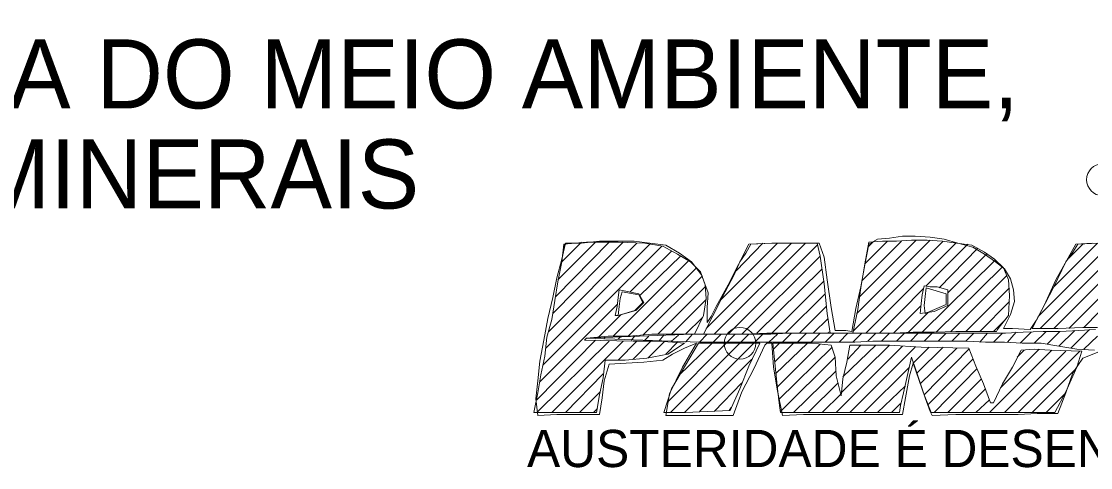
# Model space of a CAD drawing. Extents: x -4 to 42046, y -3 to 29697.
# Drawn here: x 33632 to 34171, y 1139 to 1364 of the extents above; entities that cross this region are included whole.
import ezdxf

# ---------------------------------------------------------------- set-up
doc = ezdxf.new("R2010")
doc.units = 0
doc.header["$LTSCALE"] = 32
doc.header["$PDMODE"] = 32
doc.header["$PDSIZE"] = 16
for name, color, linetype, lineweight in [('12', 7, 'Continuous', 13), ('50', 7, 'Continuous', 13), ('51', 7, 'Continuous', 13)]:
    doc.layers.add(name, color=color, linetype=linetype, lineweight=lineweight)
doc.layers.add('53', color=7, linetype='Continuous')

msp = doc.modelspace()

# ---------------------------------------------------------------- linework, layer by layer
at = {"layer": '12'}
for points in [[(34091.29, 1165.53), (34090.29, 1167.53), (34087.79, 1174.53), (34081.79, 1192.03), (34079.79, 1185.53), (34077.79, 1174.53), (34076.29, 1166.03), (34066.29, 1166.03), (34055.79, 1166.03), (34045.29, 1166.03), (34035.79, 1166.03), (34026.29, 1166.03), (34015.79, 1165.53), (34013.29, 1178.03), (34011.29, 1190.03), (34010.29, 1202.03), (34009.29, 1202.03), (34007.79, 1202.03), (34006.79, 1201.03), (34001.29, 1189.03), (33995.29, 1177.53), (33990.79, 1165.53), (33979.29, 1165.53), (33968.29, 1165.53), (33956.79, 1165.53), (33958.79, 1176.53), (33965.29, 1190.03), (33972.29, 1202.03), (33966.29, 1199.53), (33960.29, 1196.53), (33955.29, 1193.53), (33945.79, 1192.53), (33936.79, 1192.03), (33928.29, 1191.53), (33925.79, 1183.03), (33924.79, 1174.53), (33923.29, 1166.03), (33912.29, 1166.03), (33901.79, 1166.03), (33892.29, 1165.53), (33891.29, 1174.03), (33892.29, 1183.03), (33893.29, 1193.03), (33895.29, 1203.53), (33897.29, 1214.53), (33899.79, 1225.03), (33901.79, 1235.03), (33904.29, 1244.53), (33906.29, 1252.53), (33914.29, 1252.53), (33923.29, 1253.53), (33932.29, 1253.53), (33940.79, 1253.53), (33948.79, 1252.53), (33956.79, 1251.53), (33963.79, 1247.53), (33969.79, 1243.03), (33974.79, 1236.53), (33978.29, 1227.53), (33977.79, 1220.03), (33977.79, 1215.53), (33977.79, 1212.53), (33979.79, 1215.53), (33982.29, 1220.53), (33988.29, 1231.53), (33998.79, 1252.03), (34010.29, 1252.53), (34022.29, 1252.53), (34034.29, 1252.53), (34036.79, 1245.53), (34038.29, 1234.03), (34040.29, 1220.03), (34042.29, 1208.53), (34045.29, 1208.53), (34047.79, 1208.53), (34050.79, 1208.03), (34052.79, 1219.53), (34055.29, 1230.53), (34057.29, 1241.53), (34059.29, 1252.03), (34063.79, 1254.53), (34069.79, 1255.03), (34076.29, 1256.03), (34082.79, 1256.03), (34090.29, 1255.53), (34097.29, 1254.53), (34104.29, 1252.53), (34111.79, 1250.53), (34117.79, 1247.03), (34123.29, 1243.03), (34127.79, 1239.53), (34130.79, 1234.53), (34132.29, 1229.03), (34132.79, 1223.03), (34130.79, 1216.53), (34127.29, 1209.53), (34131.79, 1209.53)], [(34131.79, 1209.53), (34140.79, 1209.03), (34143.79, 1213.53), (34147.79, 1221.03), (34153.79, 1234.03), (34163.79, 1252.03), (34172.29, 1252.53)], [(34176.29, 1198.03), (34167.29, 1194.53), (34162.29, 1187.03), (34158.79, 1177.03), (34154.79, 1166.53), (34144.29, 1166.53), (34134.79, 1166.03), (34123.79, 1166.03), (34113.29, 1166.03), (34103.29, 1166.03), (34091.29, 1165.53)]]:
    msp.add_lwpolyline(points, dxfattribs=at)
for points in [[(33932.79, 1216.03), (33933.29, 1220.53), (33933.79, 1224.53), (33934.79, 1228.03), (33943.29, 1226.53), (33945.29, 1222.53), (33941.29, 1218.53)], [(34087.79, 1217.03), (34087.29, 1221.03), (34087.79, 1225.53), (34088.29, 1230.03), (34098.29, 1227.03), (34098.29, 1221.53)]]:
    msp.add_lwpolyline(points, close=True, dxfattribs=at)
at = {"layer": '50'}
for p, q in [((33897.79, 1208.03), (33942.29, 1252.53)), ((33899.79, 1217.03), (33935.29, 1253.03)), ((33901.29, 1225.53), (33928.29, 1253.03)), ((33902.29, 1234.03), (33921.29, 1253.03)), ((33904.29, 1243.03), (33914.29, 1253.03)), ((33977.29, 1209.53), (34020.29, 1252.53)), ((33981.29, 1206.53), (34027.29, 1252.53)), ((33984.79, 1224.03), (34013.29, 1252.53)), ((33992.29, 1238.53), (34005.79, 1252.53)), ((34051.29, 1208.03), (34096.79, 1253.53)), ((34053.29, 1217.03), (34090.29, 1254.03)), ((34054.79, 1225.53), (34083.29, 1254.03)), ((34055.79, 1233.53), (34075.79, 1253.53)), ((34057.29, 1242.03), (34068.79, 1253.53)), ((34057.79, 1207.03), (34103.29, 1252.53)), ((34058.79, 1250.53), (34061.29, 1253.03)), ((34144.79, 1215.53), (34181.79, 1252.53)), ((34145.79, 1209.53), (34188.79, 1252.53)), ((34152.79, 1230.53), (34174.79, 1252.53)), ((34152.79, 1209.53), (34195.79, 1252.53)), ((33894.79, 1191.03), (33954.79, 1251.03)), ((33896.29, 1199.53), (33948.79, 1252.03)), ((33905.29, 1251.03), (33906.29, 1252.03)), ((33938.79, 1228.03), (33959.79, 1248.53)), ((33988.29, 1206.53), (34033.29, 1251.53)), ((34088.29, 1231.03), (34109.29, 1252.03)), ((34094.79, 1230.03), (34114.29, 1250.03)), ((34099.29, 1227.53), (34118.79, 1247.03)), ((34160.29, 1245.03), (34167.29, 1252.03)), ((34160.29, 1209.53), (34198.79, 1248.03)), ((33930.29, 1205.53), (33968.29, 1243.53)), ((33943.79, 1226.03), (33964.29, 1246.03)), ((33995.29, 1206.53), (34034.79, 1246.03)), ((34086.29, 1207.53), (34123.29, 1244.03)), ((34167.79, 1210.03), (34200.29, 1243.03)), ((33937.79, 1205.53), (33972.29, 1240.03)), ((33945.29, 1206.03), (33975.29, 1236.03)), ((34002.79, 1207.03), (34035.79, 1239.53)), ((34093.29, 1207.53), (34126.79, 1240.53)), ((34100.79, 1208.03), (34128.79, 1236.03)), ((34010.29, 1207.03), (34036.79, 1233.53)), ((33952.79, 1206.53), (33976.79, 1230.53)), ((34017.29, 1207.03), (34037.29, 1227.03)), ((34064.79, 1207.03), (34086.79, 1229.53)), ((34108.29, 1208.03), (34130.29, 1230.03)), ((33893.29, 1182.53), (33932.29, 1221.53)), ((33959.79, 1206.53), (33977.29, 1224.03)), ((34024.29, 1207.03), (34037.79, 1220.53)), ((34071.79, 1207.03), (34085.79, 1221.03)), ((34115.29, 1208.03), (34130.29, 1223.03)), ((33922.79, 1205.03), (33934.29, 1216.53)), ((33966.79, 1206.53), (33975.29, 1215.03)), ((34031.29, 1207.03), (34038.79, 1214.53)), ((34079.29, 1207.53), (34089.29, 1217.53)), ((34122.29, 1208.03), (34128.29, 1214.03)), ((34038.29, 1207.03), (34039.79, 1208.03)), ((33891.79, 1173.53), (33921.29, 1203.53)), ((33891.79, 1167.03), (33928.29, 1203.03)), ((33899.29, 1167.03), (33935.29, 1203.03)), ((33932.79, 1193.53), (33942.29, 1203.03)), ((33940.29, 1194.03), (33949.29, 1203.03)), ((33947.79, 1194.53), (33956.29, 1203.03)), ((33956.79, 1196.53), (33962.79, 1202.53)), ((33957.79, 1172.53), (33987.29, 1202.03)), ((33959.29, 1167.03), (33994.29, 1202.03)), ((33963.29, 1185.53), (33980.29, 1202.03)), ((33966.29, 1167.03), (34001.29, 1202.03)), ((34011.29, 1199.03), (34014.29, 1202.03)), ((34011.79, 1192.53), (34021.29, 1202.03)), ((34012.29, 1186.53), (34028.29, 1202.03)), ((34013.29, 1180.03), (34034.79, 1201.53)), ((34013.79, 1173.53), (34040.79, 1200.03)), ((34042.79, 1167.03), (34076.29, 1200.53)), ((34045.29, 1177.03), (34069.79, 1201.03)), ((34046.29, 1185.03), (34062.79, 1201.03)), ((34048.79, 1194.03), (34055.29, 1201.03)), ((34049.79, 1167.03), (34082.79, 1200.03)), ((34081.79, 1192.03), (34089.79, 1200.03)), ((34083.79, 1187.03), (34096.79, 1200.03)), ((34085.29, 1181.53), (34103.79, 1199.53)), ((34087.29, 1176.03), (34109.79, 1199.03)), ((34120.29, 1167.03), (34151.79, 1198.53)), ((34125.79, 1179.53), (34145.29, 1199.03)), ((34134.29, 1195.03), (34137.79, 1198.53)), ((33973.79, 1167.53), (34000.29, 1194.03)), ((34014.79, 1167.53), (34042.29, 1195.03)), ((34089.29, 1171.03), (34111.79, 1194.03)), ((34127.79, 1167.03), (34158.79, 1198.03)), ((34134.79, 1167.03), (34165.79, 1198.03)), ((34021.29, 1167.03), (34042.79, 1188.03)), ((34056.79, 1167.03), (34079.79, 1190.03)), ((34092.29, 1167.03), (34113.79, 1189.03)), ((34141.79, 1167.03), (34163.79, 1189.03)), ((33906.29, 1167.03), (33925.29, 1186.53)), ((34099.29, 1167.03), (34116.29, 1184.03)), ((33913.29, 1167.03), (33923.79, 1177.53)), ((33981.29, 1167.53), (33995.29, 1182.03)), ((34028.79, 1167.03), (34043.79, 1182.03)), ((34063.79, 1167.03), (34077.79, 1180.53)), ((34106.29, 1167.03), (34118.29, 1179.03)), ((34035.79, 1167.03), (34045.29, 1176.53)), ((34070.79, 1167.03), (34075.29, 1171.53)), ((34113.29, 1167.03), (34120.29, 1173.53)), ((34148.79, 1167.03), (34158.29, 1176.53)), ((33920.29, 1167.03), (33922.29, 1169.03)), ((33988.79, 1168.03), (33989.79, 1169.53))]:
    msp.add_line(p, q, dxfattribs=at)
for points in [[(33890.29, 1167.03), (33892.29, 1177.03), (33893.79, 1186.03), (33895.79, 1195.53), (33896.79, 1205.03), (33899.29, 1214.03), (33900.79, 1223.53), (33902.29, 1233.03), (33904.29, 1243.03), (33905.29, 1252.03), (33916.79, 1253.03), (33932.79, 1253.03), (33946.29, 1252.53), (33955.29, 1251.03), (33962.79, 1247.03), (33969.29, 1243.03), (33974.29, 1238.03), (33976.79, 1231.53), (33977.29, 1224.53), (33975.79, 1216.03), (33971.29, 1206.53), (33960.29, 1206.53), (33949.79, 1206.53), (33938.29, 1205.53), (33927.79, 1205.53), (33916.79, 1204.53), (33916.79, 1204.53), (33916.29, 1204.03), (33915.79, 1203.53), (33940.29, 1203.03), (33953.29, 1203.03), (33960.29, 1202.53), (33966.29, 1202.03), (33957.79, 1196.53), (33947.29, 1194.53), (33936.29, 1193.53), (33926.29, 1193.53), (33925.29, 1184.53), (33923.29, 1176.03), (33921.79, 1167.03), (33911.29, 1167.03), (33901.29, 1167.03)], [(33975.79, 1206.53), (33985.29, 1225.03), (33991.29, 1236.53), (33994.29, 1243.03), (33997.29, 1247.53), (33999.79, 1252.03), (34010.29, 1252.53), (34022.29, 1252.53), (34033.29, 1252.53), (34034.79, 1246.03), (34036.79, 1232.03), (34038.29, 1217.03), (34039.79, 1207.03), (34028.79, 1207.03), (34018.29, 1207.03), (34007.79, 1207.03), (33996.79, 1206.53), (33986.29, 1206.53)], [(34051.29, 1207.03), (34053.79, 1219.03), (34055.29, 1230.03), (34057.29, 1242.03), (34059.29, 1253.03), (34066.29, 1253.53), (34073.29, 1253.53), (34080.79, 1254.03), (34088.79, 1254.03), (34096.29, 1253.53), (34103.79, 1252.53), (34111.29, 1251.53), (34117.79, 1248.03), (34122.79, 1244.53), (34127.29, 1240.03), (34129.79, 1234.03), (34130.29, 1226.03), (34129.79, 1216.03), (34129.79, 1216.03), (34125.79, 1211.03), (34124.29, 1209.03), (34123.79, 1208.03), (34112.79, 1208.03), (34103.29, 1208.03), (34092.29, 1207.53), (34081.79, 1207.53), (34071.79, 1207.03), (34061.79, 1207.03)], [(34085.29, 1217.03), (34085.79, 1222.03), (34086.29, 1226.53), (34087.29, 1231.03), (34090.29, 1230.53), (34093.79, 1230.53), (34099.29, 1229.03), (34099.29, 1221.03), (34092.29, 1218.03)], [(33932.79, 1216.03), (33932.29, 1216.03), (33932.29, 1216.03), (33931.29, 1216.03), (33932.29, 1220.53), (33932.79, 1225.03), (33933.29, 1229.03), (33943.29, 1227.03), (33945.79, 1222.53), (33941.79, 1218.53)], [(33955.79, 1167.03), (33959.79, 1179.03), (33966.79, 1191.03), (33973.29, 1202.03), (33983.79, 1202.03), (33994.29, 1202.03), (34004.29, 1202.03), (33998.79, 1190.53), (33994.29, 1179.03), (33989.29, 1168.03), (33977.79, 1167.53), (33966.79, 1167.03)], [(34014.79, 1167.03), (34014.29, 1170.53), (34013.29, 1179.03), (34010.79, 1202.03), (34020.79, 1202.03), (34030.79, 1202.03), (34040.29, 1201.03), (34042.29, 1195.03), (34042.79, 1185.53), (34045.29, 1175.53), (34046.29, 1184.03), (34048.29, 1192.53), (34049.79, 1201.03), (34051.29, 1201.03), (34054.29, 1201.03), (34059.79, 1201.03), (34069.79, 1201.03), (34085.79, 1200.03), (34109.79, 1199.53), (34113.29, 1190.53), (34117.29, 1181.53), (34120.79, 1172.03), (34121.29, 1172.03), (34121.29, 1172.03), (34122.29, 1172.03), (34126.79, 1181.53), (34131.79, 1190.03), (34136.29, 1198.53), (34142.79, 1199.03), (34150.79, 1198.53), (34166.79, 1198.03), (34164.29, 1190.03), (34158.79, 1177.53), (34153.29, 1167.03), (34142.79, 1167.03), (34132.29, 1167.03), (34121.79, 1167.03), (34111.29, 1167.03), (34100.79, 1167.03), (34090.79, 1167.03), (34087.29, 1176.03), (34083.29, 1188.03), (34080.79, 1195.03), (34076.79, 1177.03), (34075.29, 1170.53), (34074.79, 1167.03), (34064.29, 1167.03), (34055.29, 1167.03), (34045.29, 1167.03), (34034.79, 1167.03), (34025.29, 1167.03)]]:
    msp.add_lwpolyline(points, close=True, dxfattribs=at)
msp.add_lwpolyline([(34174.79, 1210.03), (34167.29, 1210.03), (34154.79, 1209.53), (34141.79, 1209.53), (34152.79, 1230.53), (34158.79, 1243.03), (34162.29, 1248.03), (34164.79, 1252.03), (34175.29, 1252.53)], dxfattribs=at)
msp.add_point((33994.29, 1202.03), dxfattribs=at)
at = {"layer": '51'}
for p, q in [((33918.79, 1204.53), (33919.29, 1204.53)), ((33925.79, 1204.03), (33926.29, 1205.03)), ((33932.79, 1204.03), (33933.79, 1205.03)), ((33939.29, 1203.53), (33941.29, 1205.53)), ((33946.29, 1203.53), (33948.29, 1205.53)), ((33953.29, 1203.03), (33955.79, 1206.03)), ((33959.79, 1203.03), (33963.29, 1206.03)), ((33966.79, 1202.53), (33970.29, 1206.53)), ((33973.79, 1202.53), (33977.79, 1206.53)), ((33980.79, 1202.53), (33984.79, 1206.53)), ((33987.79, 1202.53), (33991.79, 1206.53)), ((33994.79, 1202.53), (33998.79, 1206.53)), ((34001.79, 1202.53), (34005.79, 1206.53)), ((34008.79, 1202.53), (34013.29, 1206.53)), ((34015.79, 1202.53), (34020.29, 1207.03)), ((34023.29, 1202.53), (34027.79, 1207.03)), ((34030.29, 1202.53), (34034.79, 1207.03)), ((34037.29, 1202.53), (34041.79, 1207.03)), ((34044.29, 1202.53), (34048.79, 1207.03)), ((34051.29, 1202.53), (34055.79, 1207.03)), ((34058.79, 1203.03), (34062.79, 1207.03)), ((34065.79, 1203.03), (34069.79, 1207.03)), ((34073.29, 1203.03), (34077.29, 1207.03)), ((34080.29, 1203.03), (34084.29, 1207.03)), ((34087.29, 1203.03), (34091.29, 1207.03)), ((34094.29, 1203.03), (34098.29, 1207.03)), ((34101.29, 1203.03), (34105.29, 1207.03)), ((34108.29, 1203.03), (34112.29, 1207.03)), ((34115.29, 1202.53), (34119.29, 1207.03)), ((34122.29, 1202.53), (34126.79, 1207.03)), ((34129.29, 1202.53), (34133.79, 1207.53)), ((34135.79, 1202.03), (34141.29, 1207.53)), ((34142.79, 1202.03), (34148.79, 1208.03)), ((34149.29, 1201.53), (34155.79, 1208.03)), ((34155.29, 1200.53), (34163.29, 1208.53)), ((34161.29, 1199.53), (34170.79, 1209.03)), ((34167.79, 1199.03), (34174.79, 1205.53))]:
    msp.add_line(p, q, dxfattribs=at)
msp.add_lwpolyline([(34173.29, 1198.53), (34164.29, 1199.03), (34155.29, 1200.53), (34146.29, 1202.03), (34136.79, 1202.03), (34127.79, 1202.53), (34118.29, 1202.53), (34108.79, 1203.03), (34099.29, 1203.03), (34089.79, 1203.03), (34080.29, 1203.03), (34071.29, 1203.03), (34061.29, 1203.03), (34052.29, 1202.53), (34042.79, 1202.53), (34033.29, 1202.53), (34024.29, 1202.53), (34015.29, 1202.53), (34006.79, 1202.53), (33995.79, 1202.53), (33984.79, 1202.53), (33973.79, 1202.53), (33916.79, 1204.53), (33970.29, 1206.53), (33975.79, 1206.53), (33991.29, 1206.53), (34001.29, 1206.53), (34009.79, 1206.53), (34018.79, 1207.03), (34027.79, 1207.03), (34036.79, 1207.03), (34046.29, 1207.03), (34055.29, 1207.03), (34064.29, 1207.03), (34073.29, 1207.03), (34082.79, 1207.03), (34091.79, 1207.03), (34100.79, 1207.03), (34110.29, 1207.03), (34119.29, 1207.03), (34128.29, 1207.03), (34137.29, 1207.53), (34147.29, 1208.03), (34155.79, 1208.03), (34165.29, 1208.53), (34173.79, 1209.03)], dxfattribs=at)
msp.add_point((34177.29, 1284.53), dxfattribs=at)

# ---------------------------------------------------------------- texts
at = {"layer": '53'}
for s, height, p in [('SECRETARIA EXTRAORDINÁRIA DO MEIO AMBIENTE,', 34.83, (32931.79, 1320.53)), ('DOS RECURSOS HÍDRICOS E MINERAIS', 34.83, (32931.79, 1270.03)), ('AUSTERIDADE É DESENVOLVIMENTO', 18.77, (33886.79, 1139.53))]:
    msp.add_text(s, height=height, dxfattribs=at).set_placement(p)

doc.saveas('drawing.dxf')
